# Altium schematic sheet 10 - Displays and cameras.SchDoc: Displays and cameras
size A3; PageSetup: Record=PageOptions¦CenterHorizontal=True¦CenterVertical=True¦PrintScale=0.70¦XCorrection=1.00¦YCorrection=1.00¦PrintKind=0¦BorderSize=5000000¦LeftOffset=0¦BottomOffset=0¦Orientation=2¦PaperLength=4200¦PaperWidth=2970¦Scale=100¦PaperSource=7¦PrintQuality=600¦MediaType=1¦DitherType=10¦PaperKind=A4¦PrintScaleMode=1; Author: Juan Anzola; SheetNumber: 10; SheetTotal: 17
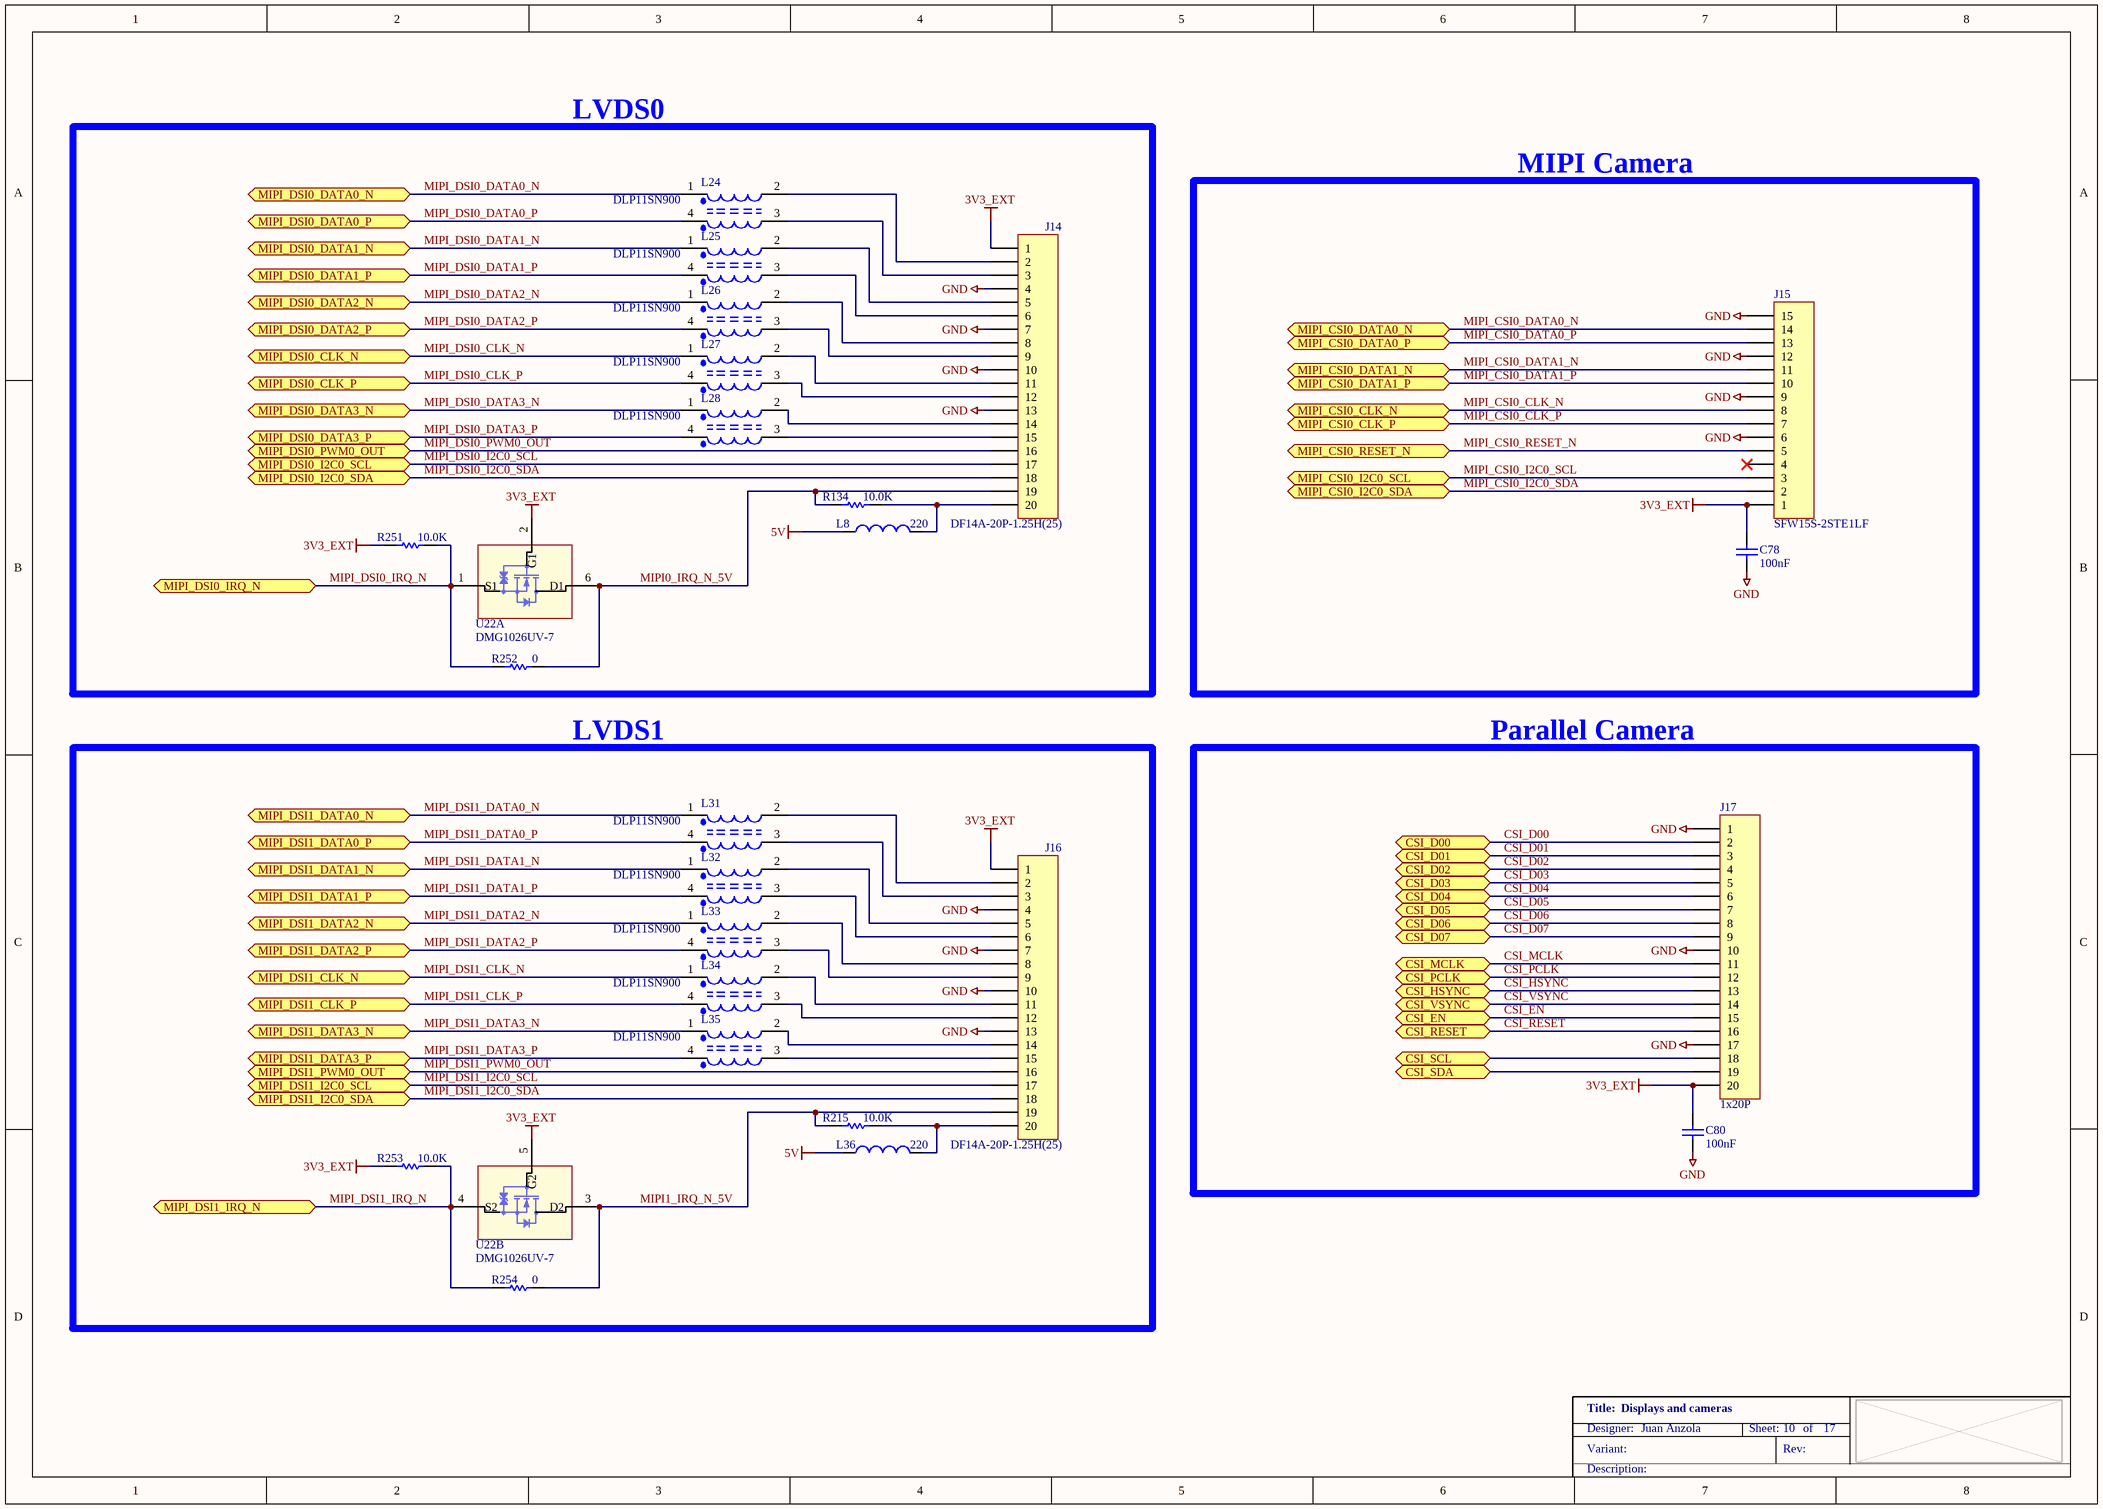
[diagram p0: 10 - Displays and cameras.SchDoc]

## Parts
C78  100nF  [CAPC1005X55N]
C80  100nF  [CAPC1005X55N]
J14  DF14A-20P-1.25H(25)  [HIROSE_DF14A-20P-1.25H]
J15  SFW15S-2STE1LF  [FCI_SFW15S-2STE1LF]
J16  DF14A-20P-1.25H(25)  [HIROSE_DF14A-20P-1.25H]
J17  1x20P  [omron_xf2m-2015-1a]
L8  220  [INDC2013X110N]
L24  DLP11SN900  [FIL_DLP11S]
L25  DLP11SN900  [FIL_DLP11S]
L26  DLP11SN900  [FIL_DLP11S]
L27  DLP11SN900  [FIL_DLP11S]
L28  DLP11SN900  [FIL_DLP11S]
L31  DLP11SN900  [FIL_DLP11S]
L32  DLP11SN900  [FIL_DLP11S]
L33  DLP11SN900  [FIL_DLP11S]
L34  DLP11SN900  [FIL_DLP11S]
L35  DLP11SN900  [FIL_DLP11S]
L36  220  [INDC2013X110N]
R134  10.0K  [RESC1005X40N]
R215  10.0K  [RESC1005X40N]
R251  10.0K  [RESC1005X40N]
R252  0  [RESC1005X40N]
R253  10.0K  [RESC1005X40N]
R254  0  [RESC1005X40N]
U22  DMG1026UV-7  [SOTFL50P160X60-6N]  (parts A,B of 2)

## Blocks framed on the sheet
LVDS0: J14 L8 L24-L28 R134 R251 R252 U22
MIPI Camera: C78 J15
LVDS1: J16 L31-L36 R215 R253 R254 U22
Parallel Camera: C80 J17

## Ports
CSI_D00 (bidir), CSI_D01 (bidir), CSI_D02 (bidir), CSI_D03 (bidir), CSI_D04 (bidir), CSI_D05 (bidir), CSI_D06 (bidir), CSI_D07 (bidir), CSI_EN (bidir), CSI_HSYNC (bidir), CSI_MCLK (bidir), CSI_PCLK (bidir), CSI_RESET (bidir), CSI_SCL (bidir), CSI_SDA (bidir), CSI_VSYNC (bidir), MIPI_CSI0_CLK_N (bidir), MIPI_CSI0_CLK_P (bidir), MIPI_CSI0_DATA0_N (bidir), MIPI_CSI0_DATA0_P (bidir), MIPI_CSI0_DATA1_N (bidir), MIPI_CSI0_DATA1_P (bidir), MIPI_CSI0_I2C0_SCL (bidir), MIPI_CSI0_I2C0_SDA (bidir), MIPI_CSI0_RESET_N (bidir), MIPI_DSI0_CLK_N (bidir), MIPI_DSI0_CLK_P (bidir), MIPI_DSI0_DATA0_N (bidir), MIPI_DSI0_DATA0_P (bidir), MIPI_DSI0_DATA1_N (bidir), MIPI_DSI0_DATA1_P (bidir), MIPI_DSI0_DATA2_N (bidir), MIPI_DSI0_DATA2_P (bidir), MIPI_DSI0_DATA3_N (bidir), MIPI_DSI0_DATA3_P (bidir), MIPI_DSI0_I2C0_SCL (bidir), MIPI_DSI0_I2C0_SDA (bidir), MIPI_DSI0_IRQ_N (bidir), MIPI_DSI0_PWM0_OUT (bidir), MIPI_DSI1_CLK_N (bidir), MIPI_DSI1_CLK_P (bidir), MIPI_DSI1_DATA0_N (bidir), MIPI_DSI1_DATA0_P (bidir), MIPI_DSI1_DATA1_N (bidir), MIPI_DSI1_DATA1_P (bidir), MIPI_DSI1_DATA2_N (bidir), MIPI_DSI1_DATA2_P (bidir), MIPI_DSI1_DATA3_N (bidir), MIPI_DSI1_DATA3_P (bidir), MIPI_DSI1_I2C0_SCL (bidir), MIPI_DSI1_I2C0_SDA (bidir), MIPI_DSI1_IRQ_N (bidir), MIPI_DSI1_PWM0_OUT (bidir)

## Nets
3V3_EXT: C78.2 C80.2 J14.1 J15.1 J16.1 J17.20 R251.1 R253.1 U22.2(G1) U22.5(G2)
5V: L8.1 L36.1
GND: C78.1 C80.1 J14.4 J14.7 J14.10 J14.13 J15.6 J15.9 J15.12 J15.15 J16.4 J16.7 J16.10 J16.13 J17.1 J17.10 J17.17
CSI_D00: J17.2 ; port CSI_D00
CSI_D01: J17.3 ; port CSI_D01
CSI_D02: J17.4 ; port CSI_D02
CSI_D03: J17.5 ; port CSI_D03
CSI_D04: J17.6 ; port CSI_D04
CSI_D05: J17.7 ; port CSI_D05
CSI_D06: J17.8 ; port CSI_D06
CSI_D07: J17.9 ; port CSI_D07
CSI_EN: J17.15 ; port CSI_EN
CSI_HSYNC: J17.13 ; port CSI_HSYNC
CSI_MCLK: J17.11 ; port CSI_MCLK
CSI_PCLK: J17.12 ; port CSI_PCLK
CSI_RESET: J17.16 ; port CSI_RESET
CSI_SCL: J17.18 ; port CSI_SCL
CSI_SDA: J17.19 ; port CSI_SDA
CSI_VSYNC: J17.14 ; port CSI_VSYNC
MIPI0_IRQ_N_5V: J14.19 R134.1 R252.2 U22.6(D1)
MIPI1_IRQ_N_5V: J16.19 R215.1 R254.2 U22.3(D2)
MIPI_CSI0_CLK_N: J15.8 ; port MIPI_CSI0_CLK_N
MIPI_CSI0_CLK_P: J15.7 ; port MIPI_CSI0_CLK_P
MIPI_CSI0_DATA0_N: J15.14 ; port MIPI_CSI0_DATA0_N
MIPI_CSI0_DATA0_P: J15.13 ; port MIPI_CSI0_DATA0_P
MIPI_CSI0_DATA1_N: J15.11 ; port MIPI_CSI0_DATA1_N
MIPI_CSI0_DATA1_P: J15.10 ; port MIPI_CSI0_DATA1_P
MIPI_CSI0_I2C0_SCL: J15.3 ; port MIPI_CSI0_I2C0_SCL
MIPI_CSI0_I2C0_SDA: J15.2 ; port MIPI_CSI0_I2C0_SDA
MIPI_CSI0_RESET_N: J15.5 ; port MIPI_CSI0_RESET_N
MIPI_DSI0_CLK_N: L27.1 ; port MIPI_DSI0_CLK_N
MIPI_DSI0_CLK_P: L27.4 ; port MIPI_DSI0_CLK_P
MIPI_DSI0_DATA0_N: L24.1 ; port MIPI_DSI0_DATA0_N
MIPI_DSI0_DATA0_P: L24.4 ; port MIPI_DSI0_DATA0_P
MIPI_DSI0_DATA1_N: L25.1 ; port MIPI_DSI0_DATA1_N
MIPI_DSI0_DATA1_P: L25.4 ; port MIPI_DSI0_DATA1_P
MIPI_DSI0_DATA2_N: L26.1 ; port MIPI_DSI0_DATA2_N
MIPI_DSI0_DATA2_P: L26.4 ; port MIPI_DSI0_DATA2_P
MIPI_DSI0_DATA3_N: L28.1 ; port MIPI_DSI0_DATA3_N
MIPI_DSI0_DATA3_P: L28.4 ; port MIPI_DSI0_DATA3_P
MIPI_DSI0_I2C0_SCL: J14.17 ; port MIPI_DSI0_I2C0_SCL
MIPI_DSI0_I2C0_SDA: J14.18 ; port MIPI_DSI0_I2C0_SDA
MIPI_DSI0_IRQ_N: R251.2 R252.1 U22.1(S1) ; port MIPI_DSI0_IRQ_N
MIPI_DSI0_PWM0_OUT: J14.16 ; port MIPI_DSI0_PWM0_OUT
MIPI_DSI1_CLK_N: L34.1 ; port MIPI_DSI1_CLK_N
MIPI_DSI1_CLK_P: L34.4 ; port MIPI_DSI1_CLK_P
MIPI_DSI1_DATA0_N: L31.1 ; port MIPI_DSI1_DATA0_N
MIPI_DSI1_DATA0_P: L31.4 ; port MIPI_DSI1_DATA0_P
MIPI_DSI1_DATA1_N: L32.1 ; port MIPI_DSI1_DATA1_N
MIPI_DSI1_DATA1_P: L32.4 ; port MIPI_DSI1_DATA1_P
MIPI_DSI1_DATA2_N: L33.1 ; port MIPI_DSI1_DATA2_N
MIPI_DSI1_DATA2_P: L33.4 ; port MIPI_DSI1_DATA2_P
MIPI_DSI1_DATA3_N: L35.1 ; port MIPI_DSI1_DATA3_N
MIPI_DSI1_DATA3_P: L35.4 ; port MIPI_DSI1_DATA3_P
MIPI_DSI1_I2C0_SCL: J16.17 ; port MIPI_DSI1_I2C0_SCL
MIPI_DSI1_I2C0_SDA: J16.18 ; port MIPI_DSI1_I2C0_SDA
MIPI_DSI1_IRQ_N: R253.2 R254.1 U22.4(S2) ; port MIPI_DSI1_IRQ_N
MIPI_DSI1_PWM0_OUT: J16.16 ; port MIPI_DSI1_PWM0_OUT
NetJ14_2: J14.2 L24.2
NetJ14_3: J14.3 L24.3
NetJ14_5: J14.5 L25.2
NetJ14_6: J14.6 L25.3
NetJ14_8: J14.8 L26.2
NetJ14_9: J14.9 L26.3
NetJ14_11: J14.11 L27.2
NetJ14_12: J14.12 L27.3
NetJ14_14: J14.14 L28.2
NetJ14_15: J14.15 L28.3
NetJ14_20: J14.20 L8.2 R134.2
NetJ16_2: J16.2 L31.2
NetJ16_3: J16.3 L31.3
NetJ16_5: J16.5 L32.2
NetJ16_6: J16.6 L32.3
NetJ16_8: J16.8 L33.2
NetJ16_9: J16.9 L33.3
NetJ16_11: J16.11 L34.2
NetJ16_12: J16.12 L34.3
NetJ16_14: J16.14 L35.2
NetJ16_15: J16.15 L35.3
NetJ16_20: J16.20 L36.2 R215.2

Not connected (* = marked no-connect by the designer): J15 4*

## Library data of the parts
C78 C80 = 1000006: CAP 100nF 16V 10% X7R 0402; Part_Type: Capacitor; Manufacturer: Murata; Manufacturer_Part_Number: GRM155R71C104KA88D; Digi_PN: 14050552; Component_Life_Cycle_State: CAD Reviewed; Area: 0,95; Project: KITT; Tolerance: 10
J14 J16 = 1001132: CONN HEADER 20POS 1.25MM R/A SMD; Part_Type: Connector; Manufacturer: Hirose; Digi_PN: 18050231; Component_Life_Cycle_State: Reviewed; Area: 206.34; Project: CCWMX6_SBC board
J15 = 1001866: CONN FFC FPC VERT 15POS 1MM SMD; Part_Type: Connector; Manufacturer: FCI; Digi_PN: 18000730; Component_Life_Cycle_State: Reviewed; Area: 128,76; Project: CCiMX6 SBC MFG TEST BOARD
J17 = 1001145: CONN FPC 20POS 0.5MM PITCH SMD; Part_Type: Connector; Manufacturer: Omron; Manufacturer_Part_Number: XF2M-2015-1A; Digi_PN: 18000675; Component_Life_Cycle_State: Reviewed; Area: 69,09; Project: CCWMX6_SBC board
L8 L36 = 1001174: FERRITE BEAD 220 OHM 2.0A 0805; Manufacturer: Wurth Electronics Inc; Manufacturer_Part_Number: 742792022; Digi_PN: 21000146; Component_Life_Cycle_State: Reviewed; Area: 4.24; Project: CCWMX6_SBC board
L24-L28 L31-L35 = 1001014: CHOKE COIL COMMON MODE 150MA SMD; Part_Type: Inductor; Manufacturer: Murata; Manufacturer_Part_Number: DLP11SN900HL2L; Component_Life_Cycle_State: Reviewed; Area: 3.94; Project: ResMed RF Test Interface Board; Digi_PN: 21000531
R134 R215 R251 R253 = 1000537: RES 10.0K OHM 1/10W 1% 0402 SMD; Part_Type: Resistor; Manufacturer: Panasonic - ECG; Manufacturer_Part_Number: ERJ-2RKF1002X; Component_Life_Cycle_State: CAD Reviewed; Area: 0.95; Project: KITT; Power_WV_SRF: 100; Digi_PN: 13051084
R252 R254 = 1000076: RES 0.0 OHM 1/10W 0402 SMD; Part_Type: Resistor; Manufacturer: Panasonic - ECG; Manufacturer_Part_Number: ERJ-2GE0R00X; Digi_PN: 13050387; Component_Life_Cycle_State: Proven; Area: 0,95; Power_WV_SRF: 10
U22 = 1001009: MOSFET DL N-CH 60V 410MA SOT-563; Part_Type: Transistor; Manufacturer: Diodes, Inc.; Digi_PN: 17050796; Component_Life_Cycle_State: Reviewed; Area: 2,89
